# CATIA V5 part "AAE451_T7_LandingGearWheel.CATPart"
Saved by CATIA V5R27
Part number: Front Landing Gear Wheel
Bounding box of the stored display mesh (mm): x 0 to 22, y -22.5 to 22.5, z -22.5 to 22.5
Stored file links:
  W:\AAE 451\Front Landing Gear Wheel.CATPart
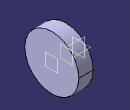
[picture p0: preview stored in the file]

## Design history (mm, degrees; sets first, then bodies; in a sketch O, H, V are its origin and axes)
Body1 (main body)
  Plane1 "Shaft": type Offset, RefPlane yz-plane, Offset 10
  Plane2 "Wheel": type Offset, RefPlane Plane1, Offset 12
  Sketch1 on yz-plane, origin (0, 0, 0), H (0, 1, 0), V (0, 0, 1)
    circle A1 centre (0, 0) radius 2.5
    radius A1 = 2.5
  Sketch2 on Plane1, origin (10, 0, 0), H (0, 1, 0), V (0, 0, 1)
    circle A1 centre (0, 0) radius 22.5
    radius A1 = 22.5
  Pad1: profile Sketch1, direction (1, 0, 0), up to Plane1
  Pad2: profile Sketch2, direction (1, 0, 0), up to Plane2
